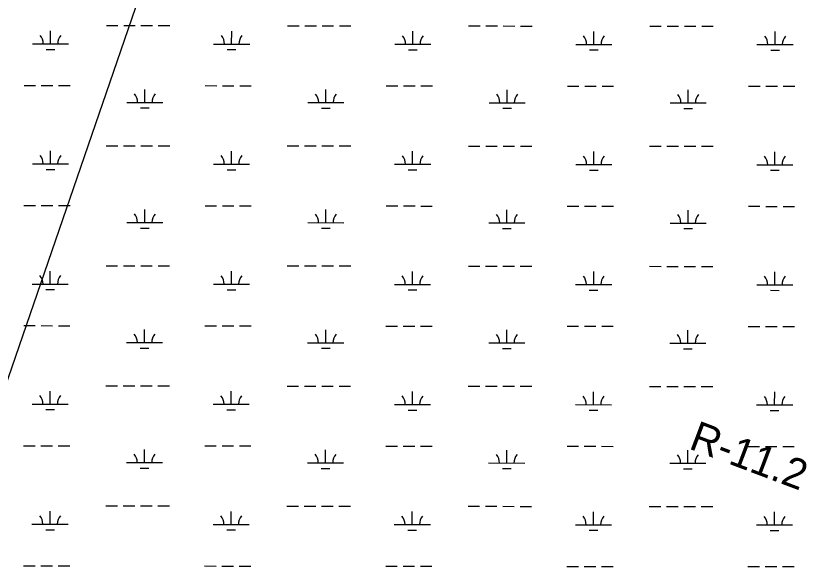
# Model space of a CAD drawing. Extents: x 3148686 to 3186545, y 916144 to 941516.
# Drawn here: x 3157647 to 3159839, y 931458 to 932988 of the extents above; entities that cross this region are included whole.
import ezdxf

# ---------------------------------------------------------------- set-up
doc = ezdxf.new("R2010")
doc.units = 0
for name, color, linetype in [('V-RIVR-RANG-IDEN', 7, 'Continuous'), ('V-TOPO-BNDY', 7, 'Continuous'), ('V-WETL-SWMP', 7, 'Continuous')]:
    doc.layers.add(name, color=color, linetype=linetype)

msp = doc.modelspace()

# ---------------------------------------------------------------- linework, layer by layer
at = {"layer": 'V-TOPO-BNDY'}
msp.add_line((3156975.7, 930095.6), (3158547.5, 934665.8), dxfattribs=at)
at = {"layer": 'V-WETL-SWMP'}
for p, q in [((3157897.4, 932960.8), (3157929.4, 932960.8)), ((3157945.4, 932960.8), (3157977.4, 932960.7)), ((3157993.4, 932960.7), (3158025.4, 932960.7)), ((3158041.4, 932960.7), (3158073.4, 932960.6)), ((3158399.3, 932960.3), (3158431.3, 932960.3)), ((3158447.3, 932960.2), (3158479.3, 932960.2)), ((3158495.3, 932960.2), (3158527.3, 932960.2)), ((3158543.3, 932960.1), (3158575.3, 932960.1)), ((3158901.2, 932959.8), (3158933.2, 932959.7)), ((3158949.2, 932959.7), (3158981.2, 932959.7)), ((3158997.2, 932959.7), (3159029.2, 932959.6)), ((3159045.2, 932959.6), (3159077.2, 932959.6)), ((3159403.1, 932959.2), (3159435.1, 932959.2)), ((3159451.1, 932959.2), (3159483.1, 932959.1)), ((3159499.1, 932959.1), (3159531.1, 932959.1)), ((3159547.1, 932959.1), (3159579.1, 932959)), ((3157742.7, 932910.2), (3157742.8, 932946.2)), ((3158244.6, 932909.7), (3158244.7, 932945.7)), ((3158746.6, 932909.2), (3158746.6, 932945.2)), ((3159248.5, 932908.7), (3159248.5, 932944.7)), ((3159750.4, 932908.1), (3159750.4, 932944.1)), ((3157692.7, 932910.3), (3157792.7, 932910.2)), ((3158194.6, 932909.8), (3158294.6, 932909.7)), ((3158696.6, 932909.2), (3158796.6, 932909.1)), ((3159198.5, 932908.7), (3159298.5, 932908.6)), ((3159700.4, 932908.2), (3159800.4, 932908.1)), ((3157730.7, 932894.8), (3157754.7, 932894.8)), ((3158232.6, 932894.3), (3158256.6, 932894.3)), ((3158734.5, 932893.8), (3158758.5, 932893.7)), ((3159236.4, 932893.2), (3159260.4, 932893.2)), ((3159738.4, 932892.7), (3159762.4, 932892.7)), ((3157669.2, 932794.9), (3157701.2, 932794.8)), ((3157717.2, 932794.8), (3157749.2, 932794.8)), ((3157765.2, 932794.8), (3157797.2, 932794.7)), ((3158004, 932748.1), (3158004, 932784.1)), ((3158171.1, 932794.4), (3158203.1, 932794.3)), ((3158219.1, 932794.3), (3158251.1, 932794.3)), ((3158267.1, 932794.3), (3158299.1, 932794.2)), ((3158505.9, 932747.6), (3158505.9, 932783.6)), ((3158673, 932793.8), (3158705, 932793.8)), ((3158721, 932793.8), (3158753, 932793.7)), ((3158769, 932793.7), (3158801, 932793.7)), ((3159007.8, 932747), (3159007.9, 932783)), ((3159174.9, 932793.3), (3159206.9, 932793.3)), ((3159222.9, 932793.2), (3159254.9, 932793.2)), ((3159270.9, 932793.2), (3159302.9, 932793.2)), ((3159509.7, 932746.5), (3159509.8, 932782.5)), ((3159676.8, 932792.8), (3159708.8, 932792.7)), ((3159724.8, 932792.7), (3159756.8, 932792.7)), ((3159772.8, 932792.7), (3159804.8, 932792.6)), ((3157954, 932748.2), (3158054, 932748)), ((3157992, 932732.7), (3158016, 932732.7)), ((3158455.9, 932747.6), (3158555.9, 932747.5)), ((3158493.9, 932732.2), (3158517.9, 932732.1)), ((3158957.8, 932747.1), (3159057.8, 932747)), ((3159459.7, 932746.6), (3159559.7, 932746.5)), ((3158995.8, 932731.6), (3159019.8, 932731.6)), ((3159497.7, 932731.1), (3159521.7, 932731.1)), ((3157897, 932628.1), (3157929, 932628.1)), ((3157945, 932628.1), (3157977, 932628.1)), ((3157993, 932628), (3158025, 932628)), ((3158041, 932628), (3158073, 932628)), ((3158398.9, 932627.6), (3158430.9, 932627.6)), ((3158446.9, 932627.6), (3158478.9, 932627.5)), ((3158494.9, 932627.5), (3158526.9, 932627.5)), ((3158542.9, 932627.5), (3158574.9, 932627.4)), ((3158900.8, 932627.1), (3158932.8, 932627.1)), ((3158948.8, 932627), (3158980.8, 932627)), ((3158996.8, 932627), (3159028.8, 932626.9)), ((3159044.8, 932626.9), (3159076.8, 932626.9)), ((3159402.8, 932626.6), (3159434.8, 932626.5)), ((3159450.8, 932626.5), (3159482.8, 932626.5)), ((3159498.8, 932626.5), (3159530.8, 932626.4)), ((3159546.8, 932626.4), (3159578.8, 932626.4)), ((3157742.4, 932577.6), (3157742.4, 932613.6)), ((3158244.3, 932577), (3158244.3, 932613)), ((3158746.2, 932576.5), (3158746.2, 932612.5)), ((3159248.1, 932576), (3159248.1, 932612)), ((3159750, 932575.4), (3159750.1, 932611.4)), ((3157692.4, 932577.6), (3157792.4, 932577.5)), ((3157730.4, 932562.1), (3157754.4, 932562.1)), ((3158194.3, 932577.1), (3158294.3, 932577)), ((3158232.3, 932561.6), (3158256.3, 932561.6)), ((3158696.2, 932576.6), (3158796.2, 932576.5)), ((3158734.2, 932561.1), (3158758.2, 932561.1)), ((3159198.1, 932576), (3159298.1, 932575.9)), ((3159236.1, 932560.6), (3159260.1, 932560.5)), ((3159700, 932575.5), (3159800, 932575.4)), ((3159738, 932560), (3159762, 932560)), ((3157668.9, 932462.2), (3157700.9, 932462.2)), ((3157716.9, 932462.2), (3157748.9, 932462.1)), ((3157764.9, 932462.1), (3157796.9, 932462.1)), ((3158003.7, 932415.4), (3158003.7, 932451.4)), ((3158170.8, 932461.7), (3158202.8, 932461.6)), ((3158218.8, 932461.6), (3158250.8, 932461.6)), ((3158266.8, 932461.6), (3158298.8, 932461.5)), ((3158505.6, 932414.9), (3158505.6, 932450.9)), ((3158672.7, 932461.2), (3158704.7, 932461.1)), ((3158720.7, 932461.1), (3158752.7, 932461.1)), ((3158768.7, 932461), (3158800.7, 932461)), ((3159007.5, 932414.4), (3159007.5, 932450.4)), ((3159174.6, 932460.6), (3159206.6, 932460.6)), ((3159222.6, 932460.6), (3159254.6, 932460.5)), ((3159270.6, 932460.5), (3159302.6, 932460.5)), ((3159509.4, 932413.8), (3159509.4, 932449.8)), ((3159676.5, 932460.1), (3159708.5, 932460.1)), ((3159724.5, 932460), (3159756.5, 932460)), ((3159772.5, 932460), (3159804.5, 932460)), ((3157953.7, 932415.5), (3158053.7, 932415.4)), ((3158455.6, 932414.9), (3158555.6, 932414.8)), ((3158957.5, 932414.4), (3159057.5, 932414.3)), ((3159459.4, 932413.9), (3159559.4, 932413.8)), ((3157991.6, 932400), (3158015.6, 932400)), ((3158493.5, 932399.5), (3158517.5, 932399.5)), ((3158995.5, 932398.9), (3159019.5, 932398.9)), ((3159497.4, 932398.4), (3159521.4, 932398.4)), ((3157896.7, 932295.5), (3157928.7, 932295.4)), ((3157944.7, 932295.4), (3157976.7, 932295.4)), ((3157992.7, 932295.4), (3158024.7, 932295.3)), ((3158040.7, 932295.3), (3158072.7, 932295.3)), ((3158398.6, 932294.9), (3158430.6, 932294.9)), ((3158446.6, 932294.9), (3158478.6, 932294.9)), ((3158494.6, 932294.8), (3158526.6, 932294.8)), ((3158542.6, 932294.8), (3158574.6, 932294.8)), ((3158900.5, 932294.4), (3158932.5, 932294.4)), ((3158948.5, 932294.4), (3158980.5, 932294.3)), ((3158996.5, 932294.3), (3159028.5, 932294.3)), ((3159044.5, 932294.3), (3159076.5, 932294.2)), ((3159402.4, 932293.9), (3159434.4, 932293.8)), ((3159450.4, 932293.8), (3159482.4, 932293.8)), ((3159498.4, 932293.8), (3159530.4, 932293.7)), ((3159546.4, 932293.7), (3159578.4, 932293.7)), ((3157742, 932244.9), (3157742.1, 932280.9)), ((3158243.9, 932244.4), (3158244, 932280.4)), ((3158745.9, 932243.8), (3158745.9, 932279.8)), ((3159247.8, 932243.3), (3159247.8, 932279.3)), ((3159749.7, 932242.8), (3159749.7, 932278.8)), ((3157692, 932244.9), (3157792, 932244.8)), ((3157730, 932229.5), (3157754, 932229.4)), ((3158193.9, 932244.4), (3158293.9, 932244.3)), ((3158231.9, 932228.9), (3158255.9, 932228.9)), ((3158695.9, 932243.9), (3158795.9, 932243.8)), ((3158733.8, 932228.4), (3158757.8, 932228.4)), ((3159197.8, 932243.4), (3159297.8, 932243.2)), ((3159235.7, 932227.9), (3159259.7, 932227.9)), ((3159699.7, 932242.8), (3159799.7, 932242.7)), ((3159737.7, 932227.4), (3159761.7, 932227.3)), ((3157668.5, 932129.5), (3157700.5, 932129.5)), ((3157716.5, 932129.5), (3157748.5, 932129.4)), ((3157764.5, 932129.4), (3157796.5, 932129.4)), ((3158003.3, 932082.8), (3158003.3, 932118.8)), ((3158170.4, 932129), (3158202.4, 932129)), ((3158218.4, 932129), (3158250.4, 932128.9)), ((3158266.4, 932128.9), (3158298.4, 932128.9)), ((3158505.2, 932082.2), (3158505.2, 932118.2)), ((3158672.3, 932128.5), (3158704.3, 932128.4)), ((3158720.3, 932128.4), (3158752.3, 932128.4)), ((3158768.3, 932128.4), (3158800.3, 932128.3)), ((3159174.2, 932127.9), (3159206.2, 932127.9)), ((3159222.2, 932127.9), (3159254.2, 932127.9)), ((3159270.2, 932127.8), (3159302.2, 932127.8)), ((3159676.1, 932127.4), (3159708.1, 932127.4)), ((3159724.1, 932127.4), (3159756.1, 932127.3)), ((3159772.1, 932127.3), (3159804.1, 932127.3)), ((3159007.1, 932081.7), (3159007.2, 932117.7)), ((3159509, 932081.2), (3159509.1, 932117.2)), ((3157953.3, 932082.8), (3158053.3, 932082.7)), ((3158455.2, 932082.3), (3158555.2, 932082.2)), ((3158957.1, 932081.7), (3159057.1, 932081.6)), ((3159459, 932081.2), (3159559, 932081.1)), ((3157991.3, 932067.3), (3158015.3, 932067.3)), ((3158493.2, 932066.8), (3158517.2, 932066.8)), ((3158995.1, 932066.3), (3159019.1, 932066.2)), ((3159497, 932065.7), (3159521, 932065.7)), ((3157741.7, 931912.2), (3157741.7, 931948.2)), ((3157896.3, 931962.8), (3157928.3, 931962.8)), ((3157944.3, 931962.7), (3157976.3, 931962.7)), ((3157992.3, 931962.7), (3158024.3, 931962.7)), ((3158040.3, 931962.6), (3158072.3, 931962.6)), ((3158243.6, 931911.7), (3158243.6, 931947.7)), ((3158398.2, 931962.3), (3158430.2, 931962.2)), ((3158446.2, 931962.2), (3158478.2, 931962.2)), ((3158494.2, 931962.2), (3158526.2, 931962.1)), ((3158542.2, 931962.1), (3158574.2, 931962.1)), ((3158745.5, 931911.2), (3158745.5, 931947.2)), ((3158900.1, 931961.7), (3158932.1, 931961.7)), ((3158948.1, 931961.7), (3158980.1, 931961.6)), ((3158996.1, 931961.6), (3159028.1, 931961.6)), ((3159044.1, 931961.6), (3159076.1, 931961.5)), ((3159247.4, 931910.6), (3159247.4, 931946.6)), ((3159402.1, 931961.2), (3159434.1, 931961.2)), ((3159450.1, 931961.2), (3159482.1, 931961.1)), ((3159498.1, 931961.1), (3159530.1, 931961.1)), ((3159546.1, 931961.1), (3159578.1, 931961)), ((3159749.3, 931910.1), (3159749.4, 931946.1)), ((3157691.7, 931912.3), (3157791.7, 931912.2)), ((3158193.6, 931911.7), (3158293.6, 931911.6)), ((3158695.5, 931911.2), (3158795.5, 931911.1)), ((3159197.4, 931910.7), (3159297.4, 931910.6)), ((3159699.3, 931910.2), (3159799.3, 931910)), ((3157729.7, 931896.8), (3157753.7, 931896.8)), ((3158231.6, 931896.3), (3158255.6, 931896.2)), ((3158733.5, 931895.7), (3158757.5, 931895.7)), ((3159235.4, 931895.2), (3159259.4, 931895.2)), ((3159737.3, 931894.7), (3159761.3, 931894.7)), ((3157668.2, 931796.9), (3157700.2, 931796.8)), ((3157716.2, 931796.8), (3157748.2, 931796.8)), ((3157764.2, 931796.8), (3157796.2, 931796.7)), ((3158170.1, 931796.3), (3158202.1, 931796.3)), ((3158218.1, 931796.3), (3158250.1, 931796.2)), ((3158266.1, 931796.2), (3158298.1, 931796.2)), ((3158672, 931795.8), (3158704, 931795.8)), ((3158720, 931795.7), (3158752, 931795.7)), ((3158768, 931795.7), (3158800, 931795.7)), ((3159173.9, 931795.3), (3159205.9, 931795.2)), ((3159221.9, 931795.2), (3159253.9, 931795.2)), ((3159269.9, 931795.2), (3159301.9, 931795.1)), ((3159675.8, 931794.7), (3159707.8, 931794.7)), ((3159723.8, 931794.7), (3159755.8, 931794.7)), ((3159771.8, 931794.6), (3159803.8, 931794.6)), ((3158003, 931750.1), (3158003, 931786.1)), ((3158504.9, 931749.5), (3158504.9, 931785.5)), ((3159006.8, 931749), (3159006.8, 931785)), ((3159508.7, 931748.5), (3159508.7, 931784.5)), ((3157953, 931750.1), (3158053, 931750)), ((3158454.9, 931749.6), (3158554.9, 931749.5)), ((3158956.8, 931749.1), (3159056.8, 931749)), ((3159458.7, 931748.5), (3159558.7, 931748.4)), ((3157990.9, 931734.7), (3158014.9, 931734.6)), ((3158492.8, 931734.1), (3158516.8, 931734.1)), ((3158994.8, 931733.6), (3159018.8, 931733.6)), ((3159496.7, 931733.1), (3159520.7, 931733)), ((3157741.3, 931579.5), (3157741.4, 931615.5)), ((3157896, 931630.1), (3157928, 931630.1)), ((3157944, 931630.1), (3157976, 931630)), ((3157992, 931630), (3158024, 931630)), ((3158040, 931630), (3158072, 931629.9)), ((3158243.2, 931579), (3158243.3, 931615)), ((3158397.9, 931629.6), (3158429.9, 931629.6)), ((3158445.9, 931629.5), (3158477.9, 931629.5)), ((3158493.9, 931629.5), (3158525.9, 931629.5)), ((3158541.9, 931629.4), (3158573.9, 931629.4)), ((3158745.2, 931578.5), (3158745.2, 931614.5)), ((3158899.8, 931629.1), (3158931.8, 931629)), ((3158947.8, 931629), (3158979.8, 931629)), ((3158995.8, 931629), (3159027.8, 931628.9)), ((3159043.8, 931628.9), (3159075.8, 931628.9)), ((3159247.1, 931578), (3159247.1, 931614)), ((3159401.7, 931628.5), (3159433.7, 931628.5)), ((3159449.7, 931628.5), (3159481.7, 931628.4)), ((3159497.7, 931628.4), (3159529.7, 931628.4)), ((3159545.7, 931628.4), (3159577.7, 931628.3)), ((3159749, 931577.4), (3159749, 931613.4)), ((3157691.3, 931579.6), (3157791.3, 931579.5)), ((3158193.2, 931579.1), (3158293.2, 931579)), ((3158695.2, 931578.5), (3158795.2, 931578.4)), ((3159197.1, 931578), (3159297.1, 931577.9)), ((3159699, 931577.5), (3159799, 931577.4)), ((3157729.3, 931564.1), (3157753.3, 931564.1)), ((3158231.2, 931563.6), (3158255.2, 931563.6)), ((3158733.1, 931563.1), (3158757.1, 931563)), ((3159235, 931562.5), (3159259, 931562.5)), ((3159737, 931562), (3159761, 931562)), ((3157667.8, 931464.2), (3157699.8, 931464.1)), ((3157715.8, 931464.1), (3157747.8, 931464.1)), ((3157763.8, 931464.1), (3157795.8, 931464)), ((3158169.7, 931463.7), (3158201.7, 931463.6)), ((3158217.7, 931463.6), (3158249.7, 931463.6)), ((3158265.7, 931463.6), (3158297.7, 931463.5)), ((3158671.6, 931463.1), (3158703.6, 931463.1)), ((3158719.6, 931463.1), (3158751.6, 931463)), ((3158767.6, 931463), (3158799.6, 931463)), ((3159173.5, 931462.6), (3159205.5, 931462.6)), ((3159221.5, 931462.5), (3159253.5, 931462.5)), ((3159269.5, 931462.5), (3159301.5, 931462.5)), ((3159675.4, 931462.1), (3159707.4, 931462)), ((3159723.4, 931462), (3159755.4, 931462)), ((3159771.4, 931462), (3159803.4, 931461.9))]:
    msp.add_line(p, q, dxfattribs=at)
for centre, start, end in [((3157687.5, 932910.8), 359.1678, 40.7115), ((3157798, 932910.7), 139.1678, 180.7115), ((3158189.4, 932910.2), 359.1678, 40.7115), ((3158299.9, 932910.1), 139.1678, 180.7115), ((3158691.3, 932909.7), 359.1678, 40.7115), ((3158801.8, 932909.6), 139.1678, 180.7115), ((3159193.2, 932909.2), 359.1678, 40.7115), ((3159303.7, 932909.1), 139.1678, 180.7115), ((3159695.1, 932908.7), 359.1678, 40.7115), ((3159805.6, 932908.5), 139.1678, 180.7115), ((3157948.8, 932748.6), 359.1678, 40.7115), ((3158059.2, 932748.5), 139.1678, 180.7115), ((3158450.7, 932748.1), 359.1678, 40.7115), ((3158561.2, 932748), 139.1678, 180.7115), ((3158952.6, 932747.6), 359.1678, 40.7115), ((3159063.1, 932747.5), 139.1678, 180.7115), ((3159454.5, 932747), 359.1678, 40.7115), ((3159565, 932746.9), 139.1678, 180.7115), ((3157687.1, 932578.1), 359.1678, 40.7115), ((3157797.6, 932578), 139.1678, 180.7115), ((3158189.1, 932577.6), 359.1678, 40.7115), ((3158299.5, 932577.5), 139.1678, 180.7115), ((3158691, 932577), 359.1678, 40.7115), ((3158801.4, 932576.9), 139.1678, 180.7115), ((3159192.9, 932576.5), 359.1678, 40.7115), ((3159303.4, 932576.4), 139.1678, 180.7115), ((3159694.8, 932576), 359.1678, 40.7115), ((3159805.3, 932575.9), 139.1678, 180.7115), ((3157948.4, 932416), 359.1678, 40.7115), ((3158058.9, 932415.8), 139.1678, 180.7115), ((3158450.3, 932415.4), 359.1678, 40.7115), ((3158560.8, 932415.3), 139.1678, 180.7115), ((3158952.2, 932414.9), 359.1678, 40.7115), ((3159062.7, 932414.8), 139.1678, 180.7115), ((3159454.1, 932414.4), 359.1678, 40.7115), ((3159564.6, 932414.3), 139.1678, 180.7115), ((3157686.8, 932245.4), 359.1678, 40.7115), ((3157797.3, 932245.3), 139.1678, 180.7115), ((3158188.7, 932244.9), 359.1678, 40.7115), ((3158299.2, 932244.8), 139.1678, 180.7115), ((3158690.6, 932244.4), 359.1678, 40.7115), ((3158801.1, 932244.2), 139.1678, 180.7115), ((3159192.5, 932243.8), 359.1678, 40.7115), ((3159303, 932243.7), 139.1678, 180.7115), ((3159694.4, 932243.3), 359.1678, 40.7115), ((3159804.9, 932243.2), 139.1678, 180.7115), ((3157948.1, 932083.3), 359.1678, 40.7115), ((3158058.5, 932083.2), 139.1678, 180.7115), ((3158450, 932082.8), 359.1678, 40.7115), ((3158560.5, 932082.6), 139.1678, 180.7115), ((3158951.9, 932082.2), 359.1678, 40.7115), ((3159062.4, 932082.1), 139.1678, 180.7115), ((3159453.8, 932081.7), 359.1678, 40.7115), ((3159564.3, 932081.6), 139.1678, 180.7115), ((3157686.4, 931912.7), 359.1678, 40.7115), ((3157796.9, 931912.6), 139.1678, 180.7115), ((3158188.4, 931912.2), 359.1678, 40.7115), ((3158298.8, 931912.1), 139.1678, 180.7115), ((3158690.3, 931911.7), 359.1678, 40.7115), ((3158800.7, 931911.6), 139.1678, 180.7115), ((3159192.2, 931911.2), 359.1678, 40.7115), ((3159302.7, 931911), 139.1678, 180.7115), ((3159694.1, 931910.6), 359.1678, 40.7115), ((3159804.6, 931910.5), 139.1678, 180.7115), ((3157947.7, 931750.6), 359.1678, 40.7115), ((3158058.2, 931750.5), 139.1678, 180.7115), ((3158449.6, 931750.1), 359.1678, 40.7115), ((3158560.1, 931750), 139.1678, 180.7115), ((3158951.5, 931749.6), 359.1678, 40.7115), ((3159062, 931749.4), 139.1678, 180.7115), ((3159453.4, 931749), 359.1678, 40.7115), ((3159563.9, 931748.9), 139.1678, 180.7115), ((3157686.1, 931580.1), 359.1678, 40.7115), ((3157796.6, 931580), 139.1678, 180.7115), ((3158188, 931579.5), 359.1678, 40.7115), ((3158298.5, 931579.4), 139.1678, 180.7115), ((3158689.9, 931579), 359.1678, 40.7115), ((3158800.4, 931578.9), 139.1678, 180.7115), ((3159191.8, 931578.5), 359.1678, 40.7115), ((3159302.3, 931578.4), 139.1678, 180.7115), ((3159693.7, 931578), 359.1678, 40.7115), ((3159804.2, 931577.8), 139.1678, 180.7115)]:
    msp.add_arc(centre, 35.2, start, end, dxfattribs=at)

# ---------------------------------------------------------------- texts
at = {"layer": 'V-RIVR-RANG-IDEN'}
msp.add_text('R-11.2', height=83, rotation=339.3273, dxfattribs=at).set_placement((3159508.5, 931789.7))

doc.saveas('drawing.dxf')
